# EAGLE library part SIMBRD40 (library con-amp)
AMP connector
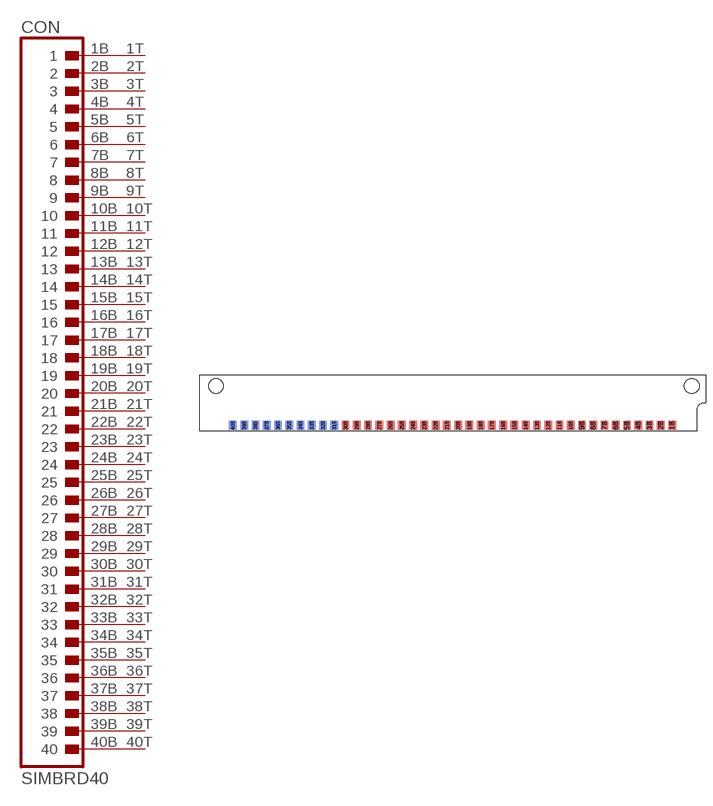
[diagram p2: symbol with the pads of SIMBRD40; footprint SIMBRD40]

Designator prefix CON

## SIMBRD40 (OC_FARNELL: unknown; OC_NEWARK: unknown)  [SIMBRD40]
1B  1  pas
1T  A1  pas
2B  2  pas
2T  A2  pas
3B  3  pas
3T  A3  pas
4B  4  pas
4T  A4  pas
5B  5  pas
5T  A5  pas
6B  6  pas
6T  A6  pas
7B  7  pas
7T  A7  pas
8B  8  pas
8T  A8  pas
9B  9  pas
9T  A9  pas
10B  10  pas
10T  A10  pas
11B  11  pas
11T  A11  pas
12B  12  pas
12T  A12  pas
13B  13  pas
13T  A13  pas
14B  14  pas
14T  A14  pas
15B  15  pas
15T  A15  pas
16B  16  pas
16T  A16  pas
17B  17  pas
17T  A17  pas
18B  18  pas
18T  A18  pas
19B  19  pas
19T  A19  pas
20B  20  pas
20T  A20  pas
21B  21  pas
21T  A21  pas
22B  22  pas
22T  A22  pas
23B  23  pas
23T  A23  pas
24B  24  pas
24T  A24  pas
25B  25  pas
25T  A25  pas
26B  26  pas
26T  A26  pas
27B  27  pas
27T  A27  pas
28B  28  pas
28T  A28  pas
29B  29  pas
29T  A29  pas
30B  30  pas
30T  A30  pas
31B  31  pas
31T  A31  pas
32B  32  pas
32T  A32  pas
33B  33  pas
33T  A33  pas
34B  34  pas
34T  A34  pas
35B  35  pas
35T  A35  pas
36B  36  pas
36T  A36  pas
37B  37  pas
37T  A37  pas
38B  38  pas
38T  A38  pas
39B  39  pas
39T  A39  pas
40B  40  pas
40T  A40  pas

## Footprint SIMBRD40 (pad centres in mm)
SIMM Modul
smd 1.778 x 2.032 bottom: 1B 49.53,-6.35; 2B 46.99,-6.35; 3B 44.45,-6.35; 4B 41.91,-6.35; 5B 39.37,-6.35; 6B 36.83,-6.35; 7B 34.29,-6.35; 8B 31.75,-6.35; 9B 29.21,-6.35; 10B 26.67,-6.35; 11B 24.13,-6.35; 12B 21.59,-6.35; 13B 19.05,-6.35; 14B 16.51,-6.35; 15B 13.97,-6.35; 16B 11.43,-6.35; 17B 8.89,-6.35; 18B 6.35,-6.35; 19B 3.81,-6.35; 20B 1.27,-6.35; 21B -1.27,-6.35; 22B -3.81,-6.35; 23B -6.35,-6.35; 24B -8.89,-6.35; 25B -11.43,-6.35; 26B -13.97,-6.35; 27B -16.51,-6.35; 28B -19.05,-6.35; 29B -21.59,-6.35; 30B -24.13,-6.35; 31B -26.67,-6.35; 32B -29.21,-6.35; 33B -31.75,-6.35; 34B -34.29,-6.35; 35B -36.83,-6.35; 36B -39.37,-6.35; 37B -41.91,-6.35; 38B -44.45,-6.35; 39B -46.99,-6.35; 40B -49.53,-6.35
smd 1.778 x 2.032: 1T 49.53,-6.35; 2T 46.99,-6.35; 3T 44.45,-6.35; 4T 41.91,-6.35; 5T 39.37,-6.35; 6T 36.83,-6.35; 7T 34.29,-6.35; 8T 31.75,-6.35; 9T 29.21,-6.35; 10T 26.67,-6.35; 11T 24.13,-6.35; 12T 21.59,-6.35; 13T 19.05,-6.35; 14T 16.51,-6.35; 15T 13.97,-6.35; 16T 11.43,-6.35; 17T 8.89,-6.35; 18T 6.35,-6.35; 19T 3.81,-6.35; 20T 1.27,-6.35; 21T -1.27,-6.35; 22T -3.81,-6.35; 23T -6.35,-6.35; 24T -8.89,-6.35; 25T -11.43,-6.35; 26T -13.97,-6.35; 27T -16.51,-6.35; 28T -19.05,-6.35; 29T -21.59,-6.35; 30T -24.13,-6.35; 31T -26.67,-6.35; 32T -29.21,-6.35; 33T -31.75,-6.35; 34T -34.29,-6.35; 35T -36.83,-6.35; 36T -39.37,-6.35; 37T -41.91,-6.35; 38T -44.45,-6.35; 39T -46.99,-6.35; 40T -49.53,-6.35
hole 3.302 at -53.34,2.54
hole 3.302 at 53.975,2.54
